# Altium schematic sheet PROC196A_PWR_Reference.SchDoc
size 431 x 279 mm; Date: Not shown in title block; ApprovedBy: Not shown in title block; CheckedBy: Not shown in title block; Author: Not shown in title block; CompanyName: Not shown in title block; Engineer: Not shown in title block; Organization: Not shown in title block; Address1: Not shown in title block; Address2: Not shown in title block; Address3: Not shown in title block; Address4: Not shown in title block; DocumentNumber: 3; Revision: Use project parameter SCH_Rev; SheetNumber: 3; SheetTotal: 25; PageSetup: Record=PageOptions¦CenterHorizontal=True¦CenterVertical=True¦PrintScale=1.00¦XCorrection=1.00¦YCorrection=1.00¦PrintKind=0¦BorderSize=5000000¦LeftOffset=0¦BottomOffset=0¦Orientation=2¦PaperLength=1000¦PaperWidth=1000¦Scale=100¦PaperSource=15¦PrintQuality=600¦MediaType=1¦DitherType=10¦PaperKind=Letter¦PrintScaleMode=1
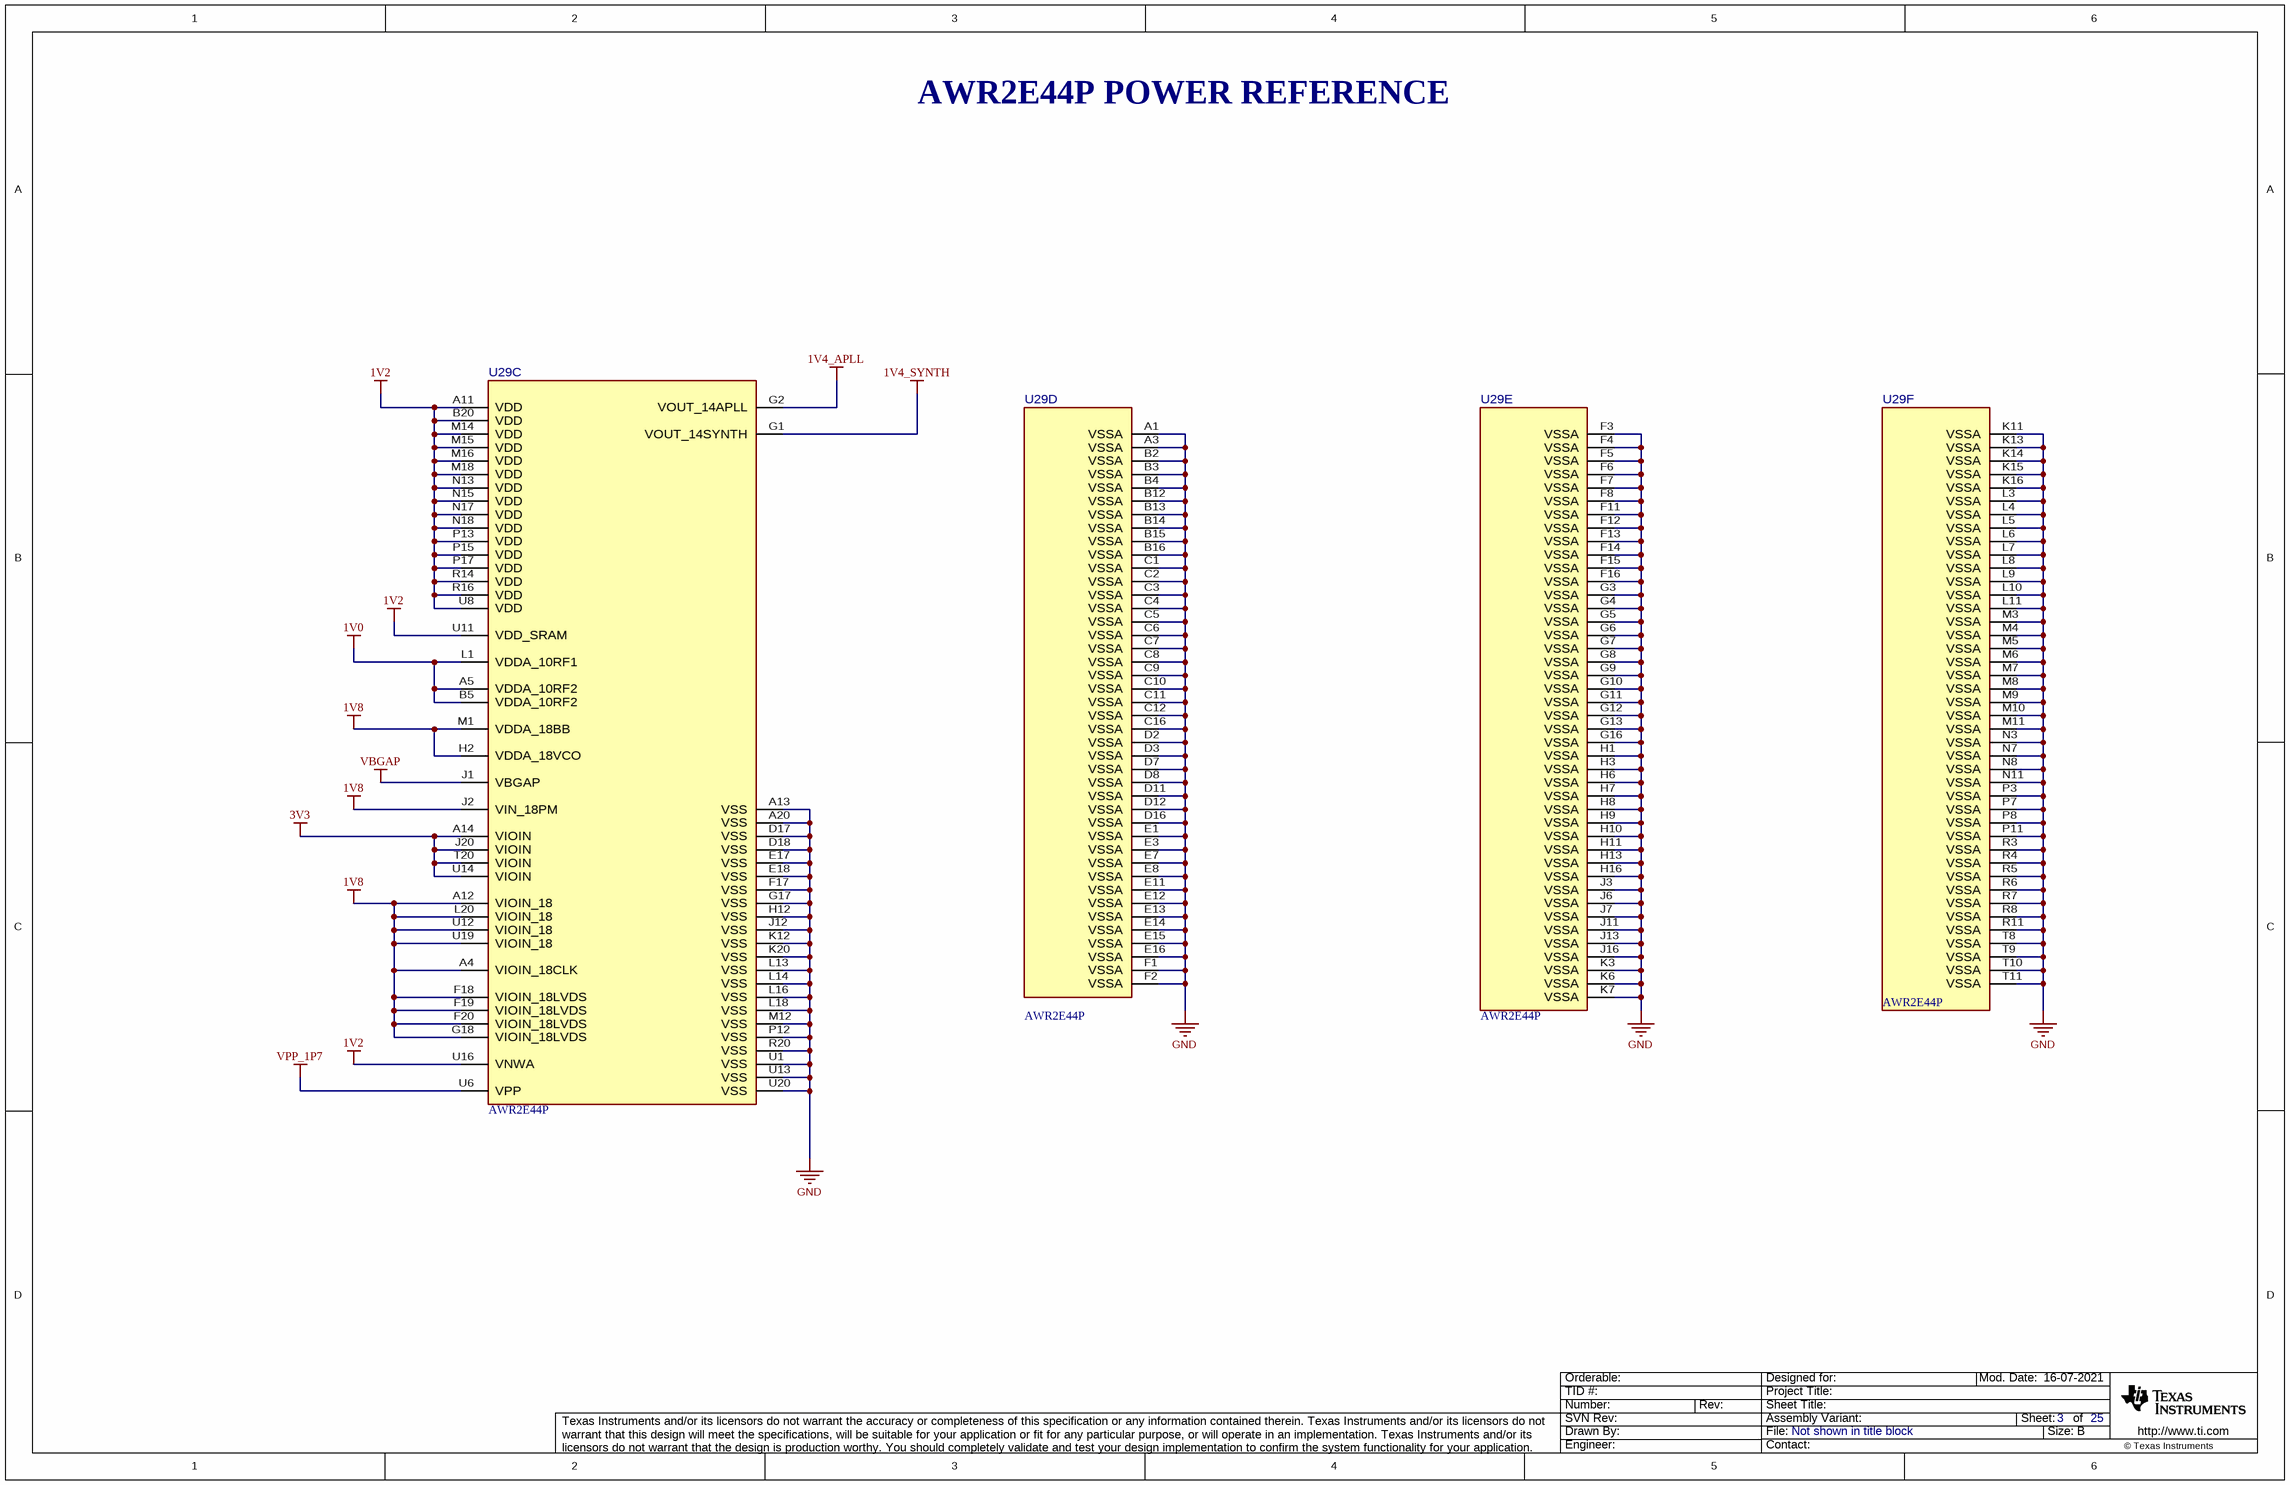
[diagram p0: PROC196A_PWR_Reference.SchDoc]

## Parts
U29  AWR2E44P  [AMX0278A-MFG]  (parts C,D,E,F of 6)

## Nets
1V0: U29.A5(VDDA_10RF2) U29.B5(VDDA_10RF2) U29.L1(VDDA_10RF1)
1V2: U29.A11(VDD) U29.B20(VDD) U29.M14(VDD) U29.M15(VDD) U29.M16(VDD) U29.M18(VDD) U29.N13(VDD) U29.N15(VDD) U29.N17(VDD) U29.N18(VDD) U29.P13(VDD) U29.P15(VDD) U29.P17(VDD) U29.R14(VDD) U29.R16(VDD) U29.U8(VDD) U29.U11(VDD_SRAM) U29.U16(VNWA)
1V4_APLL: U29.G2(VOUT_14APLL)
1V4_SYNTH: U29.G1(VOUT_14SYNTH)
1V8: U29.A4(VIOIN_18CLK) U29.A12(VIOIN_18) U29.F18(VIOIN_18LVDS) U29.F19(VIOIN_18LVDS) U29.F20(VIOIN_18LVDS) U29.G18(VIOIN_18LVDS) U29.H2(VDDA_18VCO) U29.J2(VIN_18PM) U29.L20(VIOIN_18) U29.M1(VDDA_18BB) U29.U12(VIOIN_18) U29.U19(VIOIN_18)
3V3: U29.A14(VIOIN) U29.J20(VIOIN) U29.T20(VIOIN) U29.U14(VIOIN)
GND: U29.A1(VSSA) U29.A3(VSSA) U29.A13(VSS) U29.A20(VSS) U29.B2(VSSA) U29.B3(VSSA) U29.B4(VSSA) U29.B12(VSSA) U29.B13(VSSA) U29.B14(VSSA) U29.B15(VSSA) U29.B16(VSSA) U29.C1(VSSA) U29.C2(VSSA) U29.C3(VSSA) U29.C4(VSSA) U29.C5(VSSA) U29.C6(VSSA) U29.C7(VSSA) U29.C8(VSSA) U29.C9(VSSA) U29.C10(VSSA) U29.C11(VSSA) U29.C12(VSSA) U29.C16(VSSA) U29.D2(VSSA) U29.D3(VSSA) U29.D7(VSSA) U29.D8(VSSA) U29.D11(VSSA) U29.D12(VSSA) U29.D16(VSSA) U29.D17(VSS) U29.D18(VSS) U29.E1(VSSA) U29.E3(VSSA) U29.E7(VSSA) U29.E8(VSSA) U29.E11(VSSA) U29.E12(VSSA) U29.E13(VSSA) U29.E14(VSSA) U29.E15(VSSA) U29.E16(VSSA) U29.E17(VSS) U29.E18(VSS) U29.F1(VSSA) U29.F2(VSSA) U29.F3(VSSA) U29.F4(VSSA) U29.F5(VSSA) U29.F6(VSSA) U29.F7(VSSA) U29.F8(VSSA) U29.F11(VSSA) U29.F12(VSSA) U29.F13(VSSA) U29.F14(VSSA) U29.F15(VSSA) U29.F16(VSSA) U29.F17(VSS) U29.G3(VSSA) U29.G4(VSSA) U29.G5(VSSA) U29.G6(VSSA) U29.G7(VSSA) U29.G8(VSSA) U29.G9(VSSA) U29.G10(VSSA) U29.G11(VSSA) U29.G12(VSSA) U29.G13(VSSA) U29.G16(VSSA) U29.G17(VSS) U29.H1(VSSA) U29.H3(VSSA) U29.H6(VSSA) U29.H7(VSSA) U29.H8(VSSA) U29.H9(VSSA) U29.H10(VSSA) U29.H11(VSSA) U29.H12(VSS) U29.H13(VSSA) U29.H16(VSSA) U29.J3(VSSA) U29.J6(VSSA) U29.J7(VSSA) U29.J11(VSSA) U29.J12(VSS) U29.J13(VSSA) U29.J16(VSSA) U29.K3(VSSA) U29.K6(VSSA) U29.K7(VSSA) U29.K11(VSSA) U29.K12(VSS) U29.K13(VSSA) U29.K14(VSSA) U29.K15(VSSA) U29.K16(VSSA) U29.K20(VSS) U29.L3(VSSA) U29.L4(VSSA) U29.L5(VSSA) U29.L6(VSSA) U29.L7(VSSA) U29.L8(VSSA) U29.L9(VSSA) U29.L10(VSSA) U29.L11(VSSA) U29.L13(VSS) U29.L14(VSS) U29.L16(VSS) U29.L18(VSS) U29.M3(VSSA) U29.M4(VSSA) U29.M5(VSSA) U29.M6(VSSA) U29.M7(VSSA) U29.M8(VSSA) U29.M9(VSSA) U29.M10(VSSA) U29.M11(VSSA) U29.M12(VSS) U29.N3(VSSA) U29.N7(VSSA) U29.N8(VSSA) U29.N11(VSSA) U29.P3(VSSA) U29.P7(VSSA) U29.P8(VSSA) U29.P11(VSSA) U29.P12(VSS) U29.R3(VSSA) U29.R4(VSSA) U29.R5(VSSA) U29.R6(VSSA) U29.R7(VSSA) U29.R8(VSSA) U29.R11(VSSA) U29.R20(VSS) U29.T8(VSSA) U29.T9(VSSA) U29.T10(VSSA) U29.T11(VSSA) U29.U1(VSS) U29.U13(VSS) U29.U20(VSS)
VBGAP: U29.J1(VBGAP)
VPP_1P7: U29.U6(VPP)

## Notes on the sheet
- AWR2E44P POWER REFERENCE

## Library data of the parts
U29 = CMP-0122080-1: Manufacturer: Texas Instruments; SizeZ_mm: 1.234mm; Standoff Height: 0.216mm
